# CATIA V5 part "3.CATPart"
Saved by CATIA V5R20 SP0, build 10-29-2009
Part number: 3
Bounding box of the stored display mesh (mm): x -10 to 10, y -10 to 210, z -4 to 4
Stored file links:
  E:\Ehsan\Amoozesh\CATIA\CATIA Course\Advanced\Exercises\DMU Kinematic\11\3.CATPart
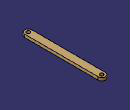
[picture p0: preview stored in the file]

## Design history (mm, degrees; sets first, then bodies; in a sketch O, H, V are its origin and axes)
Body1 (main body)
  Sketch1 on xy-plane, origin (0, 0, 0), H (1, 0, 0), V (0, 1, 0)
    construction line L1 (0, 0) -> (0, 200)
    line L2 (-10, 0) -> (-10, 200)
    line L3 (10, 200) -> (10, 0)
    arc A1 centre (0, 200) radius 10 from (-10, 200) to (10, 200) cw
    arc A2 centre (0, 0) radius 10 from (10, 0) to (-10, 0) cw
    circle A3 centre (0, 0) radius 5
    circle A4 centre (0, 200) radius 5
    distance L1 L2 = 10
    length L1 = 200
    radius A4 = 5
    radius A3 = 5
    vertical: L1 V
    tangency: A1 L2, A2 L2, A1 L3, A2 L3
  Pad1: profile Sketch1, direction (0, 0, 1), length 4, mirrored extent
